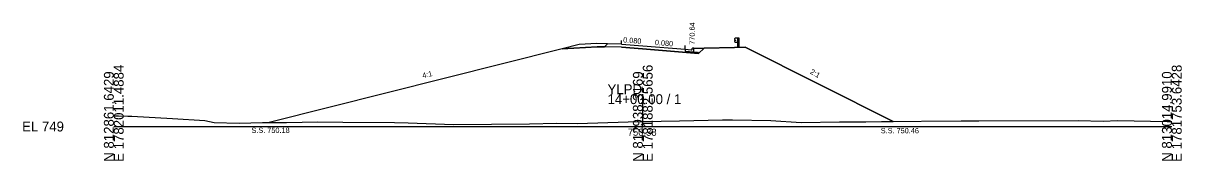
# Model space of a CAD drawing. Extents: x -26 to 353, y -10 to 9080.
# Drawn here: x -25.7 to 302.8, y 3990.3 to 4029.2 of the extents above; entities that cross this region are included whole.
import ezdxf

# ---------------------------------------------------------------- set-up
doc = ezdxf.new("R2010")
doc.units = 0
for name, color, linetype in [('Exist Cross Section Cell', 7, 'Continuous'), ('Exist XS Center Line Elevation Label', 7, 'Continuous'), ('Exist XS Ground Line', 7, 'Continuous'), ('Prop XS Dump Level', 7, 'Continuous'), ('Prop XS Earthwork Shape', 7, 'Continuous'), ('Prop XS EOT Tick Mark', 7, 'Continuous'), ('Prop XS Finish Grade', 7, 'Continuous'), ('Prop XS Finish Grade CurbGutter', 7, 'Continuous'), ('Prop XS Finish Grade Earthwork', 7, 'Continuous'), ('Prop XS Finish Grade Paved Shoulder', 7, 'Continuous'), ('Prop XS Finish Grade Pavement', 7, 'Continuous'), ('Prop XS Guardrail', 7, 'Continuous'), ('Prop XS Hydro Elevations', 7, 'Continuous'), ('Prop XS Pvmt Edge Slope', 7, 'Continuous'), ('Prop XS SE Text', 7, 'Continuous'), ('Prop XS Side Slope Text', 7, 'Continuous'), ('Prop XS SS Elevation Text', 7, 'Continuous'), ('Prop XS Subgrade CurbGutter', 7, 'Continuous'), ('Prop XS Subgrade Earthwork', 7, 'Continuous'), ('Scratch_Level_3', 7, 'Continuous')]:
    doc.layers.add(name, color=color, linetype=linetype)

msp = doc.modelspace()

# ---------------------------------------------------------------- linework, layer by layer
at = {"layer": 'Exist Cross Section Cell'}
for p, q in [((150, 4000), (150, 4009.14)), ((0, 4000), (150, 4000)), ((150, 4000), (300, 4000))]:
    msp.add_line(p, q, dxfattribs=at)
at = {"layer": 'Exist XS Ground Line'}
for p, q in [((0, 4003.05), (1.37, 4003.01)), ((1.37, 4003.01), (3.94, 4002.94)), ((3.94, 4002.94), (4.42, 4002.94)), ((4.42, 4002.94), (5.12, 4002.91)), ((5.12, 4002.91), (16.64, 4002.24)), ((16.64, 4002.24), (25.82, 4001.68)), ((25.82, 4001.68), (28.43, 4001.17)), ((150, 4001.38), (160.37, 4001.63)), ((160.37, 4001.63), (172.59, 4001.93)), ((172.59, 4001.93), (175.4, 4001.88)), ((175.4, 4001.88), (186.32, 4001.67)), ((186.32, 4001.67), (194.9, 4001.17)), ((217.69, 4001.43), (240.26, 4001.61)), ((240.26, 4001.61), (245.29, 4001.6)), ((245.29, 4001.6), (273.4, 4001.66)), ((273.4, 4001.66), (280.54, 4001.5)), ((280.54, 4001.5), (284.61, 4001.67)), ((284.61, 4001.67), (298.71, 4001.42)), ((28.43, 4001.17), (35.59, 4000.99)), ((35.59, 4000.99), (42.2, 4001.18)), ((42.2, 4001.18), (48.95, 4001.18)), ((48.95, 4001.18), (57.88, 4001.35)), ((57.88, 4001.35), (64.95, 4001.24)), ((64.95, 4001.24), (79.64, 4001.1)), ((79.64, 4001.1), (83.46, 4001.04)), ((83.46, 4001.04), (96.35, 4000.6)), ((96.35, 4000.6), (117.85, 4000.74)), ((117.85, 4000.74), (125.51, 4000.9)), ((125.51, 4000.9), (131.45, 4000.85)), ((131.45, 4000.85), (145.81, 4001.28)), ((145.81, 4001.28), (150, 4001.38)), ((194.9, 4001.17), (205.81, 4001.33)), ((205.81, 4001.33), (213.22, 4001.36)), ((213.22, 4001.36), (217.69, 4001.43)), ((298.71, 4001.42), (300, 4001.44))]:
    msp.add_line(p, q, dxfattribs=at)
at = {"layer": 'Prop XS Dump Level'}
for p, q in [((144, 4023.32), (150, 4022.84)), ((150, 4022.84), (162, 4021.88))]:
    msp.add_line(p, q, dxfattribs=at)
at = {"layer": 'Prop XS Earthwork Shape'}
msp.add_lwpolyline([(143.95, 4022.41), (139.1, 4022.5), (137.02, 4022.54), (127.17, 4021.95), (44.08, 4001.18), (48.95, 4001.18), (57.88, 4001.35), (64.95, 4001.24), (79.64, 4001.1), (83.46, 4001.04), (96.35, 4000.6), (117.85, 4000.74), (125.51, 4000.9), (131.45, 4000.85), (145.81, 4001.28), (150, 4001.38), (160.37, 4001.63), (172.59, 4001.93), (175.4, 4001.88), (186.32, 4001.67), (194.9, 4001.17), (205.81, 4001.33), (213.22, 4001.36), (217.69, 4001.43), (220.97, 4001.46), (179, 4022.44), (176, 4022.38), (167.39, 4022.2), (165.84, 4020.66), (149.93, 4021.93)], close=True, dxfattribs=at)
at = {"layer": 'Prop XS EOT Tick Mark'}
for p, q in [((144, 4023.32), (144, 4024.32)), ((162, 4021.88), (162, 4022.88))]:
    msp.add_line(p, q, dxfattribs=at)
at = {"layer": 'Prop XS Finish Grade'}
for p, q in [((132, 4023.16), (127.17, 4021.95)), ((137, 4023.46), (132, 4023.16)), ((140, 4023.4), (137, 4023.46)), ((164.5, 4022.14), (167.39, 4022.2))]:
    msp.add_line(p, q, dxfattribs=at)
at = {"layer": 'Prop XS Finish Grade CurbGutter'}
for p, q in [((162, 4021.88), (163.75, 4021.67)), ((163.75, 4021.67), (163.87, 4021.7)), ((163.87, 4021.7), (163.97, 4021.79)), ((163.97, 4021.79), (164.03, 4022.04)), ((164.03, 4022.04), (164.12, 4022.13)), ((164.25, 4022.14), (164.12, 4022.13)), ((164.5, 4022.14), (164.25, 4022.14))]:
    msp.add_line(p, q, dxfattribs=at)
at = {"layer": 'Prop XS Finish Grade Earthwork'}
for p, q in [((127.17, 4021.95), (44.08, 4001.18)), ((167.39, 4022.2), (176, 4022.38)), ((176, 4022.38), (179, 4022.44)), ((179, 4022.44), (220.97, 4001.46))]:
    msp.add_line(p, q, dxfattribs=at)
at = {"layer": 'Prop XS Finish Grade Paved Shoulder'}
msp.add_line((144, 4023.32), (140, 4023.4), dxfattribs=at)
at = {"layer": 'Prop XS Finish Grade Pavement'}
for p, q in [((144, 4023.32), (150, 4022.84)), ((150, 4022.84), (162, 4021.88))]:
    msp.add_line(p, q, dxfattribs=at)
at = {"layer": 'Prop XS Guardrail'}
for p, q in [((176.03, 4024.76), (176, 4024.7)), ((176, 4024.7), (176.03, 4024.64)), ((176.32, 4024.96), (176.03, 4024.76)), ((176.03, 4024.64), (176.32, 4024.44)), ((176.82, 4024.96), (176.32, 4024.96)), ((177.32, 4024.96), (176.82, 4024.96)), ((176.82, 4024.96), (176.82, 4022.46)), ((177.32, 4022.46), (177.32, 4024.96)), ((176.03, 4024.15), (176, 4024.09)), ((176, 4024.09), (176.03, 4024.03)), ((176.32, 4024.35), (176.03, 4024.15)), ((176.03, 4024.03), (176.32, 4023.83)), ((176.32, 4024.44), (176.32, 4024.35)), ((176.32, 4023.83), (176.82, 4023.83))]:
    msp.add_line(p, q, dxfattribs=at)
at = {"layer": 'Prop XS Pvmt Edge Slope'}
for p, q in [((140, 4023.4), (139.1, 4022.5)), ((164.5, 4021.1), (165.5, 4021.02)), ((165.5, 4021.02), (165.84, 4020.66))]:
    msp.add_line(p, q, dxfattribs=at)
at = {"layer": 'Prop XS Subgrade CurbGutter'}
for p, q in [((162, 4021.88), (162, 4021.3)), ((162, 4021.3), (164.5, 4021.1)), ((164.5, 4021.1), (164.5, 4022.14))]:
    msp.add_line(p, q, dxfattribs=at)
at = {"layer": 'Prop XS Subgrade Earthwork'}
for p, q in [((137.02, 4022.54), (127.17, 4021.95)), ((139.1, 4022.5), (137.02, 4022.54)), ((143.95, 4022.41), (139.1, 4022.5)), ((143.95, 4022.41), (149.93, 4021.93)), ((149.93, 4021.93), (165.84, 4020.66)), ((165.84, 4020.66), (167.39, 4022.2))]:
    msp.add_line(p, q, dxfattribs=at)
at = {"layer": 'Scratch_Level_3'}
for p, q in [((132, 4023.16), (127.17, 4021.95)), ((127.17, 4021.95), (137.02, 4022.54)), ((137, 4023.46), (132, 4023.16)), ((140, 4023.4), (137, 4023.46)), ((137.02, 4022.54), (139.1, 4022.5)), ((139.1, 4022.5), (140, 4023.4))]:
    msp.add_line(p, q, dxfattribs=at)

# ---------------------------------------------------------------- texts
at = {"layer": 'Exist Cross Section Cell'}
for s, p in [('N 812861.6429', (0, 3990)), ('E 1782011.4884', (2.8, 3990)), ('N 812938.3169', (150, 3990)), ('E 1781882.5656', (152.8, 3990)), ('N 813014.9910', (300, 3990)), ('E 1781753.6428', (302.8, 3990))]:
    msp.add_text(s, height=2.8, rotation=90, dxfattribs=at).set_placement(p)
for s, p in [('YLPD', (140, 4009.14)), ('14+00.00 / 1', (140, 4006.34)), ('EL 749', (-26, 3998.6))]:
    msp.add_text(s, height=2.8, dxfattribs=at).set_placement(p)
at = {"layer": 'Exist XS Center Line Elevation Label'}
msp.add_text('750.38', height=2, dxfattribs=at).set_placement((145.73, 3997.38))
at = {"layer": 'Prop XS Dump Level'}
msp.add_text('Case4', height=0.04, dxfattribs=at).set_placement((132, 4023.12))
at = {"layer": 'Prop XS Hydro Elevations'}
msp.add_text('770.64', height=1.5, rotation=90, dxfattribs=at).set_placement((164.75, 4023.14))
at = {"layer": 'Prop XS SE Text'}
for p in [(144.38, 4023.79), (153.38, 4023.07)]:
    msp.add_text('0.080', height=1.5, rotation=355.4261, dxfattribs=at).set_placement(p)
at = {"layer": 'Prop XS Side Slope Text'}
for s, rotation, p in [('4:1', 14.0362, (87.68, 4013.63)), ('2:1', 329.9894, (197.27, 4015.08))]:
    msp.add_text(s, height=1.5, rotation=rotation, dxfattribs=at).set_placement(p)
at = {"layer": 'Prop XS SS Elevation Text'}
for s, p in [('S.S. 750.18', (39.04, 3998.18)), ('S.S. 750.46', (217.47, 3998.08))]:
    msp.add_text(s, height=1.5, dxfattribs=at).set_placement(p)

doc.saveas('drawing.dxf')
